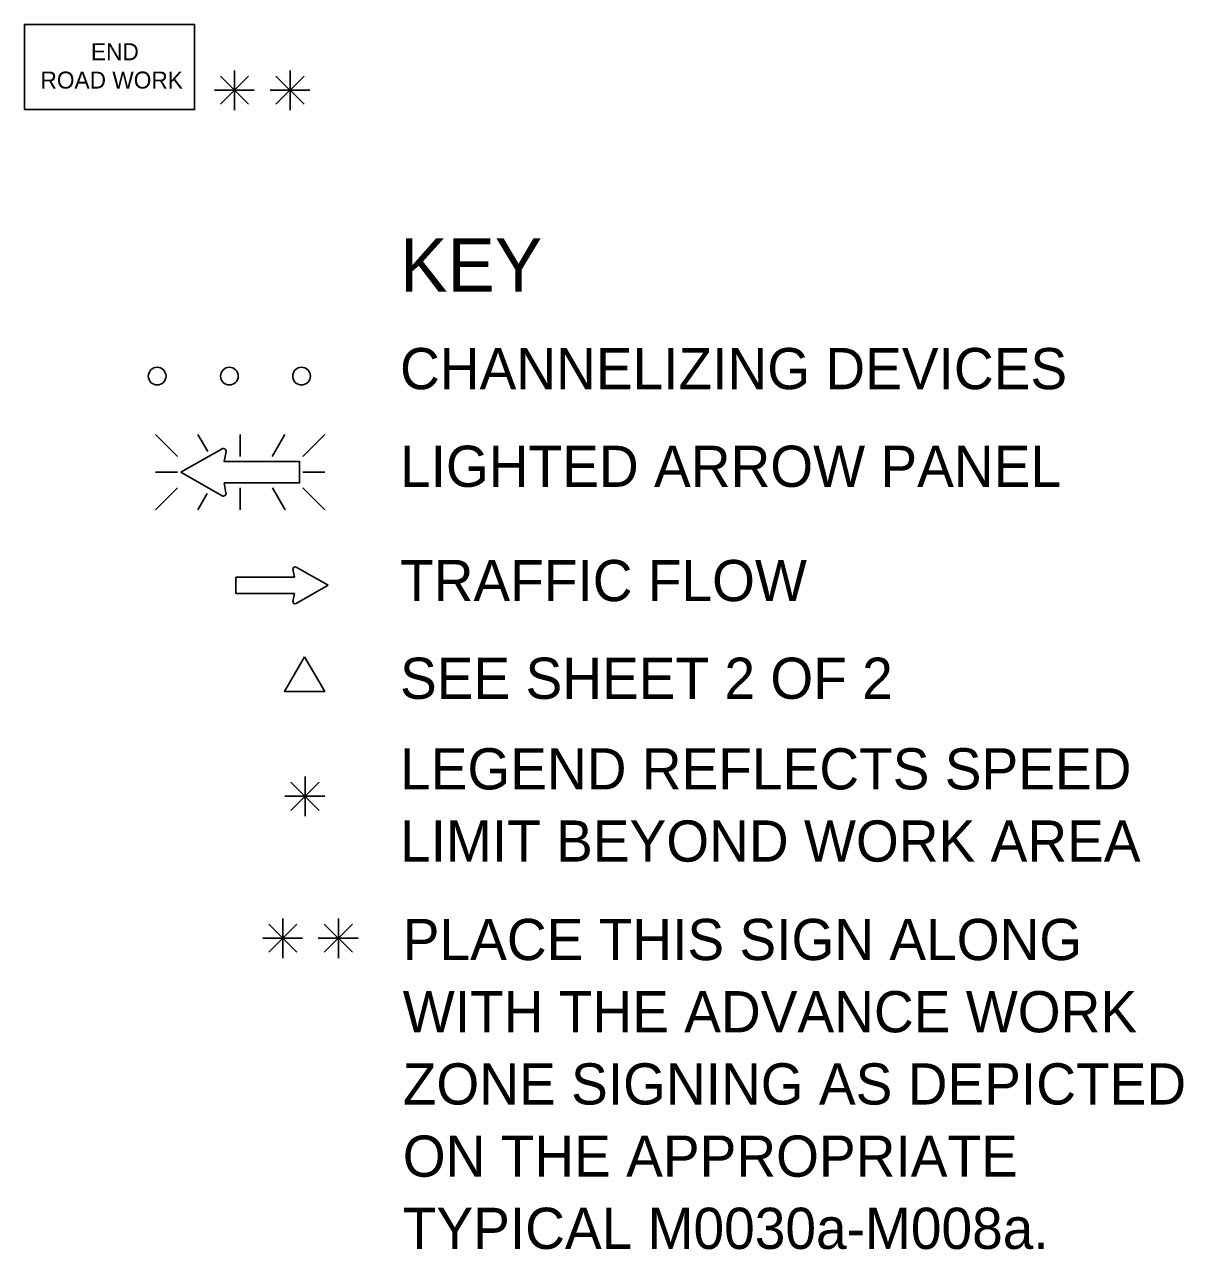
# Model space of a CAD drawing. Extents: x 16284 to 18474, y 5417 to 6974.
# Drawn here: x 17165.2 to 17426.9, y 6528.3 to 6804.8 of the extents above; entities that cross this region are included whole.
import ezdxf

# ---------------------------------------------------------------- set-up
doc = ezdxf.new("R2010")
doc.units = 0
for name, color, linetype in [('MT_SCRATCH_LEVEL_E', 7, 'Continuous'), ('TRAFFIC_SIGNS_PR', 7, 'Continuous'), ('TYPICAL_TEXT_DIMEN_EX', 7, 'Continuous'), ('TYPICAL_TEXT_DIMEN_PR', 7, 'Continuous')]:
    doc.layers.add(name, color=color, linetype=linetype)

msp = doc.modelspace()

# ---------------------------------------------------------------- linework, layer by layer
at = {"layer": 'MT_SCRATCH_LEVEL_E'}
for p, q in [((17225.81, 6681.88), (17226.12, 6680.1)), ((17233.73, 6678.25), (17226.49, 6682.36)), ((17226.12, 6680.1), (17212.87, 6680.1)), ((17212.87, 6680.1), (17212.87, 6676.36)), ((17212.87, 6676.36), (17226.12, 6676.36)), ((17226.12, 6676.36), (17225.81, 6674.58)), ((17226.49, 6674.1), (17233.73, 6678.25))]:
    msp.add_line(p, q, dxfattribs=at)
for centre, start, end in [((17226.27, 6681.95), 60.4248, 189.9638), ((17226.27, 6674.51), 170.0362, 299.7731)]:
    msp.add_arc(centre, 0.463, start, end, dxfattribs=at)
at = {"layer": 'TRAFFIC_SIGNS_PR'}
for p, q in [((17194.8, 6712.26), (17199.73, 6707.33)), ((17206.56, 6708.44), (17204.35, 6712.26)), ((17213.88, 6707.33), (17213.88, 6712.26)), ((17221.12, 6707.33), (17223.97, 6712.26)), ((17228.03, 6707.33), (17232.97, 6712.26)), ((17199.73, 6703.77), (17194.8, 6703.77)), ((17228.03, 6703.77), (17232.97, 6703.77)), ((17194.8, 6695.28), (17199.73, 6700.21)), ((17204.31, 6695.28), (17206.42, 6698.94)), ((17213.88, 6700.21), (17213.88, 6695.28)), ((17224.01, 6695.28), (17221.16, 6700.21)), ((17228.03, 6700.21), (17232.97, 6695.28))]:
    msp.add_line(p, q, dxfattribs=at)
msp.add_lwpolyline([(17165.18, 6785.64), (17203.58, 6785.64), (17203.58, 6804.84), (17165.18, 6804.84)], close=True, dxfattribs=at)
for points in [[(17209.81, 6709.05), (17200.52, 6703.77), (17209.81, 6698.45)], [(17210.68, 6699.08), (17210.28, 6701.35), (17227.3, 6701.35), (17227.3, 6706.15), (17210.28, 6706.15), (17210.69, 6708.43)]]:
    msp.add_lwpolyline(points, dxfattribs=at)
for centre in [(17195.14, 6725.46), (17211.44, 6725.46), (17227.74, 6725.46)]:
    msp.add_circle(centre, 2, dxfattribs=at)
for centre, radius, start, end in [((17210.1, 6708.52), 0.598, 350.7308, 118.8916), ((17210.1, 6698.97), 0.597, 241.4833, 9.9593)]:
    msp.add_arc(centre, radius, start, end, dxfattribs=at)
at = {"layer": 'TYPICAL_TEXT_DIMEN_PR'}
for p, q in [((17212.6, 6790.01), (17212.6, 6794.47)), ((17225.16, 6790.01), (17225.16, 6794.47)), ((17215.79, 6793.2), (17209.41, 6786.82)), ((17209.42, 6793.2), (17215.79, 6786.82)), ((17221.97, 6793.2), (17228.35, 6786.82)), ((17228.35, 6793.2), (17221.97, 6786.82)), ((17212.6, 6790.01), (17208.07, 6790.01)), ((17212.6, 6790.01), (17215.79, 6790.01)), ((17212.6, 6790.01), (17217.08, 6790.01)), ((17212.6, 6790.01), (17212.6, 6785.51)), ((17225.16, 6790.01), (17220.63, 6790.01)), ((17225.16, 6790.01), (17228.35, 6790.01)), ((17225.16, 6790.01), (17229.64, 6790.01)), ((17225.16, 6790.01), (17225.16, 6785.51)), ((17228.53, 6630.63), (17228.53, 6635.09)), ((17225.34, 6633.82), (17231.72, 6627.44)), ((17231.72, 6633.82), (17225.34, 6627.44)), ((17228.53, 6630.63), (17224, 6630.63)), ((17228.53, 6630.63), (17231.72, 6630.63)), ((17228.53, 6630.63), (17233.01, 6630.63)), ((17228.53, 6630.63), (17228.53, 6626.13)), ((17226.7, 6601.78), (17220.32, 6595.41)), ((17220.33, 6601.78), (17226.7, 6595.41)), ((17223.51, 6598.6), (17223.51, 6603.05)), ((17232.88, 6601.78), (17239.25, 6595.41)), ((17239.25, 6601.78), (17232.88, 6595.41)), ((17236.07, 6598.6), (17236.07, 6603.05)), ((17223.51, 6598.6), (17218.98, 6598.6)), ((17223.51, 6598.6), (17226.7, 6598.6)), ((17223.51, 6598.6), (17227.99, 6598.6)), ((17223.51, 6598.6), (17223.51, 6594.1)), ((17236.07, 6598.6), (17231.53, 6598.6)), ((17236.07, 6598.6), (17239.25, 6598.6)), ((17236.07, 6598.6), (17240.54, 6598.6)), ((17236.07, 6598.6), (17236.07, 6594.1))]:
    msp.add_line(p, q, dxfattribs=at)
msp.add_lwpolyline([(17228.44, 6662.08), (17223.92, 6654.24), (17232.97, 6654.24)], close=True, dxfattribs=at)

# ---------------------------------------------------------------- texts
at = {"layer": 'TRAFFIC_SIGNS_PR'}
for s, p in [('END', (17180.18, 6796.77)), ('ROAD WORK', (17168.79, 6790.38))]:
    msp.add_text(s, height=3.831, dxfattribs=at).set_placement(p)
at = {"layer": 'TYPICAL_TEXT_DIMEN_EX'}
for s, height, p in [('KEY', 12, (17249.98, 6744.56)), ('CHANNELIZING DEVICES', 9.3, (17249.98, 6722.51)), ('LIGHTED ARROW PANEL', 9.3, (17249.98, 6700.46)), ('TRAFFIC FLOW', 9.3, (17249.98, 6674.66)), ('SEE SHEET 2 OF 2', 9.3, (17249.98, 6652.61)), ('LEGEND REFLECTS SPEED', 9.3, (17249.98, 6632.16)), ('LIMIT BEYOND WORK AREA', 9.3, (17249.98, 6615.86)), ('PLACE THIS SIGN ALONG', 9.3, (17250.6, 6593.63)), ('WITH THE ADVANCE WORK', 9.3, (17250.6, 6577.33)), ('ZONE SIGNING AS DEPICTED', 9.3, (17250.6, 6561.03)), ('ON THE APPROPRIATE', 9.3, (17250.6, 6544.73)), ('TYPICAL M0030a-M008a.', 9.3, (17250.6, 6528.43))]:
    msp.add_text(s, height=height, dxfattribs=at).set_placement(p)

doc.saveas('drawing.dxf')
